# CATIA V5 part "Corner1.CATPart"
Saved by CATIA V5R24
Part number: Part1
Bounding box of the stored display mesh (mm): x -50 to 510.985, y -117.725 to 74, z -50 to 139.049
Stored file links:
  \\cdl-main\htdocs\wp-content\uploads\2016\CAD\example\05_GSD\Wireframe\Corner1.CATPart
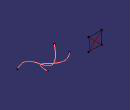
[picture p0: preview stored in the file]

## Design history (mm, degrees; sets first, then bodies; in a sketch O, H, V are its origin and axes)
External parameters (linked from other documents)
  External.Material = "None"
Set1
  DatumSurface1
  DatumCurve1 "Curve.1"
  DatumCurve2 "Curve.2"
  Line1 "Line.1": type PtPt, FirstPoint Point2, SecondPoint Point3
  Line2 "Line.2": type PtPt, FirstPoint Point1, SecondPoint Point4
  Curve1: Elements (Point5; Point6; Point7; Point8)
  Curve2: Elements (Point9; Point10; Point11; Point12)
  Sketch1 "Sketch.1" on zx-plane, origin (0, 0, 0), H (-1, 0, 0), V (0, 0, 1)
    line L1 (-210, 200) -> (-150, 90)
    line L2 (-150, 90) -> (-40, 190)
    line L3 (-40, 190) -> (40, 80)
    line L4 (40, 80) -> (90, 230)
Set2 "Geometrical_Set.2"
  Point1 "Point.3": (-50, 0, 50)
  Point2 "Point.1": (50, 0, 50)
  Point3 "Point.2": (-50, 0, -50)
  Point4 "Point.4": (50, 0, -50)
  Point5 "Point.5": type OnPlane, Support zx-plane, H -321.484, V 139.049, Direction (-1, 0, 0)
  Point6 "Point.6": type OnPlane, Support zx-plane, H -367.985, V 16.132, Direction (-1, 0, 0)
  Point7 "Point.7": (43, -100, 0), relative to Point6
  Point8 "Point.8": (100, 0, 0), relative to Point7
  Point9 "Point.9": type OnPlane, Support zx-plane, H -201.695, V 24.258, Direction (-1, 0, 0)
  Point10 "Point.10": type OnPlane, Support zx-plane, H -385.492, V 39.022, Direction (-1, 0, 0)
  Point11 "Point.11": type OnPlane, Support zx-plane, H -427.97, V 55.484, Direction (-1, 0, 0)
  Point12 "Point.12": (21, 74, 0), relative to Point11
Body1 (main body)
